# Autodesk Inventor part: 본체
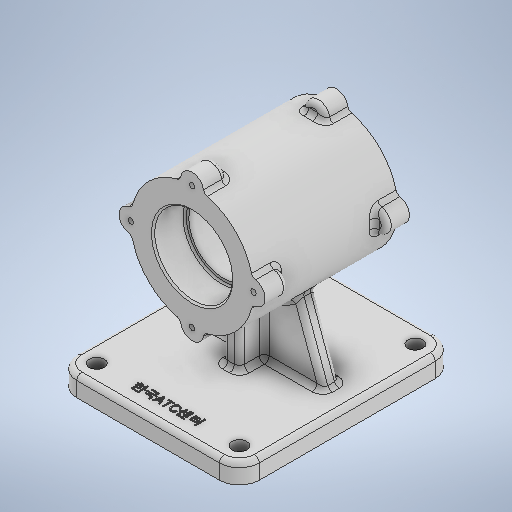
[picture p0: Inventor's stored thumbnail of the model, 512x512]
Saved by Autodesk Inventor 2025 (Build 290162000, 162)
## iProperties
Created: 2024-08
Part Number: 본체
Material: 일반
Document SubType Name: Modeling
Designer: SAMSUNG
Density: 1 g/cm^3
Appearance: 기본값
Author: SAMSUNG
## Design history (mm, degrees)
sketch "스케치1"
  geometry: L1 (55, 70)-(-55, 70); L2 (-55, 70)-(-55, -60); L3 (-55, -60)-(55, -60); L4 (55, -60)-(55, 70); L5 (55, 70)-(-55, -60); L6 (-55, 70)-(55, -60); L7 (0, 0)-(0, 5)
  constraints: 14 end point, 2 parallel, 1 horizontal, 1 midpoint, 1 perpendicular, 1 vertical
  dimensions: "d0" = 110 distance of L2.end L3.end; "d1" = 130 distance of L1.end L2.end; "d67" = 5 distance of L7.end L7.start
extrude "돌출1" new body sketch "스케치1" distance "d2" = 12; taper "d3" = 0 deg
sketch "스케치2"
  geometry: L1 (-55, 0)-(55, 0) reference; C1 r 37 at (0, 82); 4 further points
  constraints: 3 midpoint, 1 centre point, 1 vertical alignment
  dimensions: "d5" = 37 radius of C1; "d6" = 82 distance of C1.centre point (0, 0)
extrude "돌출2" join sketch "스케치2" stored distance "d7" = 87; taper "d8" = 0 deg
sketch "스케치3"
  geometry: L1 (103, 24.5)-(82, 24.5); L2 (82, 24.5)-(82, 0); L3 (82, 0)-(103, 0); L4 (103, 0)-(103, 24.5); L5 (105.5, 43.5)-(82, 43.5); L6 (82, 43.5)-(82, 24.5); L7 (82, 24.5)-(105.5, 24.5); L8 (105.5, 24.5)-(105.5, 43.5); L9 (124.874, 0)-(25.376, 0); L10 (45, -43.5)-(119, -43.5) reference; L11 (82, -43.5)-(82, 78.341); L12 (119, 43.5)-(45, 43.5) reference; L13 (103, 0)-(103, -24.5); L14 (82, -24.5)-(82, 0); L15 (82, -24.5)-(105.5, -24.5); L16 (103, -24.5)-(82, -24.5); L17 (82, -43.5)-(82, -24.5); L18 (105.5, -43.5)-(82, -43.5); L19 (105.5, -24.5)-(105.5, -43.5); 6 further points
  constraints: 34 end point, 7 point on line, 5 symmetric about line, 4 parallel, 3 horizontal, 2 perpendicular, 1 midpoint, 1 vertical
  dimensions: "d9" = 19 distance of L7.end L5.start; "d10" = 24.5 distance of L3.end L1.start (derived); "d11" = 23.5 distance of L5.start L5.end; "d12" = 21 distance of L1.start L1.end
sketch "스케치4"
  geometry: L1 (-5, 20)-(5, 20); L2 (5, 20)-(5, -20); L3 (5, -20)-(-5, -20); L4 (-5, -20)-(-5, 20); L5 (-5, 20)-(5, -20); L6 (5, 20)-(-5, -20); L7 (-55, -70)-(55, -70) reference; 5 further points
  constraints: 12 end point, 4 midpoint, 2 parallel, 1 coincident, 1 horizontal, 1 perpendicular
  dimensions: "d20" = 10 distance of L1.start L1.end; "d22" = 40 distance of L1.end L2.end; "d69" = 50 distance between parallel lines of L7 L3
extrude "돌출3" join sketch "스케치4" stored distance "d23" = 87; taper "d24" = 0 deg
sketch "스케치5"
  geometry: L1 (25.336, 55.036)-(41, 12); L2 (5, 12)-(5, 45.339) reference; L3 (55, 12)-(-55, 12) reference; C1 r 37 at (0, 82) reference; A1 r 37 centre (0, 82) between (5, 45.339) and (25.336, 55.036) reference; 1 further point
  constraints: 2 end point, 1 point on circle, 1 point on line
  dimensions: "d25" = 14 distance of L1.end L3.start; "d26" = 110 deg angle of L1 L3
feature "리브1" sketch "스케치5" dims "d27" = 1, "d28" = 10, "d29" = 0, "d30" = 0, "d31" = 1, "d32" = 1
revolve "회전2" stored, may be unused: angle "d33" = 90 deg
sketch "스케치6"
  geometry: C1 r 7 at (0, 37); 2 further points
  constraints: 1 centre point, 1 vertical alignment, 1 other
  dimensions: "d35" = 7 radius of C1
extrude "돌출4" join sketch "스케치6" distance "d36" = 14; taper "d37" = 0 deg
sketch "스케치7"
  geometry: A1 r 7 centre (0, 119) between (6.969, 118.338) and (-6.969, 118.338) reference; 2 further points
  constraints: 1 coincident
hole "구멍1" sketch "스케치7" at (0, 119) diameter "d41" = 3.242; stored, may be unused: countersink angle "d45" = 90 deg, drill point angle "d47" = 120 deg; dims "d42" = 8, "d43" = 4, "d44" = 2, "d46" = 10
sketch "스케치8"
  geometry: L1 (-43, 48)-(43, 48); L2 (43, 48)-(43, -58); L3 (43, -58)-(-43, -58); L4 (-43, -58)-(-43, 48); L5 (-43, 48)-(43, -58); L6 (43, 48)-(-43, -58); L7 (-55, -70)-(55, -70) reference; 1 further point
  constraints: 12 end point, 2 midpoint, 2 parallel, 1 horizontal, 1 perpendicular
  dimensions: "d51" = 86 distance of L1.start L1.end; "d52" = 106 distance of L1.end L2.end; "d75" = 12 distance from line of L2.end L7
hole "구멍2" sketch "스케치8" at (-43, -58), (43, -58), (43, 48), (-43, 48) diameter "d53" = 9; stored, may be unused: countersink angle "d57" = 90 deg, drill point angle "d59" = 0 deg; dims "d54" = 8, "d55" = 4, "d56" = 2, "d58" = 10
sketch "스케치9"
  geometry: L1 (-55, -70)-(55, -70) reference; L2 (77, 0)-(-77, 0) reference; 3 further points
  constraints: 1 midpoint, 1 vertical alignment, 1 other
  dimensions: "d60" = 12 distance from line of L1 point (0, -58); "d68" = 58 distance from line of point (0, -58) L2 (derived)
feature "엠보싱1" sketch "스케치9" dims "d0" = 110, "d1" = 130, "d9" = 19, "d10" = 24.5 (derived), "d11" = 23.5, "d12" = 21, "d61" = 0.5, "d62" = 0, "d67" = 5
fillet "모깎기1" dims "d63" = 12
sketch "스케치12"
  geometry: 1 further point
fillet "모깎기2" dims "d70" = 3
fillet "모깎기3" dims "d71" = 3
fillet "모깎기4" dims "d72" = 3
fillet "모깎기5" dims "d73" = 3
fillet "모깎기6" dims "d74" = 3
fillet "모깎기7" dims "d80" = 1
chamfer "모따기3" distance "d81" = 1; stored, may be unused: second distance "d82" = 2, angle "d83" = 45 deg
chamfer "모따기4" distance "d84" = 1; stored, may be unused: second distance "d85" = 2, angle "d86" = 45 deg
feature "Ϳ耀΁耀΃耀΅耀·耀Ή耀΋耀΍耀" dims "d0" = 110, "d1" = 130, "d2" = 12, "d3" = 0, "d5" = 37, "d6" = 82, "d7" = 87, "d8" = 0, "d9" = 19, "d10" = 24.5 (derived), "d11" = 23.5, "d12" = 21, "d20" = 10, "d22" = 40, "d23" = 87, "d24" = 0, "d25" = 14, "d26" = 110 deg, "d27" = 1, "d28" = 10, "d29" = 0, "d30" = 0, "d31" = 1, "d32" = 1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
node "솔리드1"
mirror "미러1"
pattern_circular "원형 패턴1" dims angle "d39" = 360 deg
mirror "미러2"
pattern_circular "원형 패턴2" dims angle "d49" = 360 deg
mirror "미러3"
node "투영된 루프1"
feature "A9D066F2-1C7D-4E18-AEED-F7BC21143FA4" dims "d53" = 9, "d54" = 8, "d55" = 4, "d56" = 2, "d57" = 90 deg, "d58" = 10, "d59" = 0
